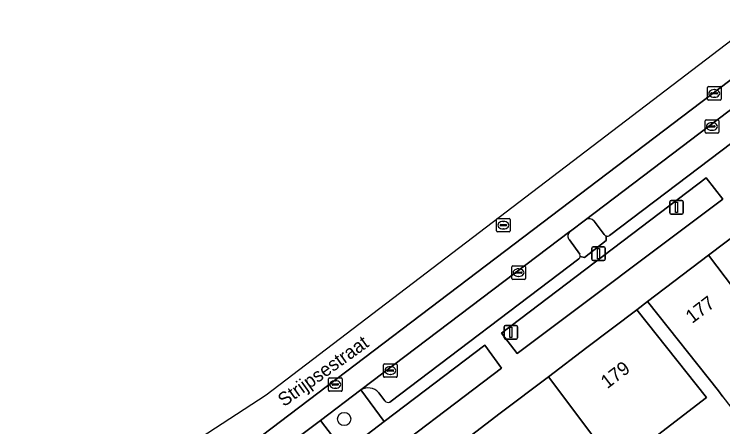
# Model space of a CAD drawing. Extents: x 159371 to 159986, y 382987 to 383597.
# Drawn here: x 159435.3 to 159487.5, y 383451 to 383481.4 of the extents above; entities that cross this region are included whole.
import ezdxf

# ---------------------------------------------------------------- set-up
doc = ezdxf.new("R2010")
doc.units = 0
for name, color, linetype in [('IMGEO_Boom', 7, 'Continuous'), ('IMGEO_Erf', 7, 'Continuous'), ('IMGEO_Groenvoorziening', 7, 'Continuous'), ('IMGEO_Kolk', 7, 'Continuous'), ('IMGEO_Lichtmast', 7, 'Continuous'), ('IMGEO_Openbare_ruimte_label', 7, 'Continuous'), ('IMGEO_Pand', 7, 'Continuous'), ('IMGEO_Pand_nummerreeks', 7, 'Continuous'), ('IMGEO_Parkeervlak_open', 7, 'Continuous'), ('IMGEO_Rijbaan_lokaal_gesloten', 7, 'Continuous'), ('IMGEO_Rijbaan_regionaal_open', 7, 'Continuous'), ('IMGEO_Rioolput', 7, 'Continuous'), ('IMGEO_Voetpad_open', 7, 'Continuous')]:
    doc.layers.add(name, color=color, linetype=linetype)

msp = doc.modelspace()

# ---------------------------------------------------------------- linework, layer by layer
at = {"layer": 'IMGEO_Boom'}
msp.add_circle((159459.611, 383451.55), 0.489, dxfattribs=at)
at = {"layer": 'IMGEO_Erf'}
msp.add_lwpolyline([(159487.559, 383453.189), (159487.219, 383453.635), (159481.987, 383460.213), (159481.199, 383459.608), (159486.357, 383453.128), (159482.085, 383449.87)], dxfattribs=at)
at = {"layer": 'IMGEO_Groenvoorziening'}
for points in [[(159472.377, 383456.378), (159487.545, 383467.769), (159486.332, 383469.328), (159471.229, 383457.872)], [(159471.23, 383455.311), (159469.992, 383456.988), (159462.575, 383451.365), (159459.638, 383449.137), (159460.912, 383447.483)], [(159460.832, 383453.708), (159457.863, 383451.442), (159459.638, 383449.137), (159462.575, 383451.365)]]:
    msp.add_lwpolyline(points, close=True, dxfattribs=at)
for points in [[(159477.407, 383466.243), (159476.315, 383465.414), (159476.264, 383465.375)], [(159478.804, 383465.148), (159478.062, 383466.146)], [(159477.024, 383463.535), (159477.339, 383463.475), (159478.937, 383464.718), (159478.954, 383465.057)], [(159476.226, 383464.764), (159477.01, 383463.705)]]:
    msp.add_lwpolyline(points, dxfattribs=at)
for centre, radius, start, end in [((159477.678, 383465.811), 0.51, 41.0938, 122.0586), ((159476.549, 383465.051), 0.432, 131.2827, 221.5997), ((159479.041, 383465.369), 0.324, 223.0627, 254.4497), ((159476.694, 383463.593), 0.335, 349.9501, 19.4656)]:
    msp.add_arc(centre, radius, start, end, dxfattribs=at)
at = {"layer": 'IMGEO_Kolk'}
for p, q in [((159486.243, 383472.699), (159486.243, 383473.551)), ((159486.318, 383473.625), (159487.17, 383473.625)), ((159486.731, 383473.405), (159486.756, 383473.405)), ((159487.244, 383473.551), (159487.244, 383472.699)), ((159486.502, 383473.119), (159486.502, 383473.131)), ((159486.94, 383473.082), (159486.542, 383473.082)), ((159486.545, 383473.168), (159486.943, 383473.168)), ((159486.754, 383472.845), (159486.729, 383472.845)), ((159486.986, 383473.131), (159486.986, 383473.119)), ((159487.17, 383472.625), (159486.318, 383472.625)), ((159471.979, 383461.919), (159471.979, 383462.771)), ((159472.054, 383462.845), (159472.906, 383462.845)), ((159472.281, 383462.388), (159472.679, 383462.388)), ((159472.467, 383462.625), (159472.492, 383462.625)), ((159472.98, 383462.771), (159472.98, 383461.919)), ((159472.906, 383461.845), (159472.054, 383461.845)), ((159472.238, 383462.339), (159472.238, 383462.351)), ((159472.676, 383462.302), (159472.278, 383462.302)), ((159472.49, 383462.065), (159472.465, 383462.065)), ((159472.722, 383462.351), (159472.722, 383462.339)), ((159462.596, 383455.624), (159463.448, 383455.624)), ((159462.521, 383454.698), (159462.521, 383455.55)), ((159462.78, 383455.118), (159462.78, 383455.13)), ((159463.218, 383455.081), (159462.82, 383455.081)), ((159462.823, 383455.167), (159463.221, 383455.167)), ((159463.009, 383455.404), (159463.034, 383455.404)), ((159463.264, 383455.13), (159463.264, 383455.118)), ((159463.522, 383455.55), (159463.522, 383454.698)), ((159463.448, 383454.624), (159462.596, 383454.624)), ((159463.032, 383454.844), (159463.007, 383454.844))]:
    msp.add_line(p, q, dxfattribs=at)
for points in [[(159486.243, 383472.699), (159486.243, 383473.551)], [(159486.318, 383473.625), (159487.17, 383473.625)], [(159487.244, 383473.551), (159487.244, 383472.699)], [(159487.17, 383472.625), (159486.318, 383472.625)], [(159471.979, 383461.919), (159471.979, 383462.771)], [(159472.054, 383462.845), (159472.906, 383462.845)], [(159472.98, 383462.771), (159472.98, 383461.919)], [(159472.906, 383461.845), (159472.054, 383461.845)], [(159462.596, 383455.624), (159463.448, 383455.624)], [(159462.521, 383454.698), (159462.521, 383455.55)], [(159463.522, 383455.55), (159463.522, 383454.698)], [(159463.448, 383454.624), (159462.596, 383454.624)]]:
    msp.add_lwpolyline(points, dxfattribs=at)
for centre, radius, start, end in [((159486.32, 383473.549), 0.0765, 91.552, 178.448), ((159486.32, 383473.549), 0.0765, 91.552, 178.448), ((159487.168, 383473.549), 0.0765, 1.552, 88.448), ((159487.168, 383473.549), 0.0765, 1.552, 88.448), ((159486.542, 383473.128), 0.0403, 85.8775, 175.7526), ((159486.539, 383473.118), 0.0366, 178.938, 274.7102), ((159486.943, 383473.125), 0.043, 264.8664, 352.4533), ((159486.947, 383473.13), 0.0386, 1.7309, 96.639), ((159486.32, 383472.701), 0.0765, 181.552, 268.448), ((159486.32, 383472.701), 0.0765, 181.552, 268.448), ((159487.168, 383472.701), 0.0765, 271.552, 358.448), ((159487.168, 383472.701), 0.0765, 271.552, 358.448), ((159472.056, 383462.769), 0.0765, 91.552, 178.448), ((159472.056, 383462.769), 0.0765, 91.552, 178.448), ((159472.278, 383462.348), 0.0403, 85.8775, 175.7526), ((159472.683, 383462.35), 0.0386, 1.7309, 96.639), ((159472.904, 383462.769), 0.0765, 1.552, 88.448), ((159472.904, 383462.769), 0.0765, 1.552, 88.448), ((159472.056, 383461.921), 0.0765, 181.552, 268.448), ((159472.056, 383461.921), 0.0765, 181.552, 268.448), ((159472.275, 383462.338), 0.0366, 178.938, 274.7102), ((159472.679, 383462.345), 0.043, 264.8664, 352.4533), ((159472.904, 383461.921), 0.0765, 271.552, 358.448), ((159472.904, 383461.921), 0.0765, 271.552, 358.448), ((159462.598, 383455.548), 0.0765, 91.552, 178.448), ((159462.598, 383455.548), 0.0765, 91.552, 178.448), ((159463.446, 383455.548), 0.0765, 1.552, 88.448), ((159463.446, 383455.548), 0.0765, 1.552, 88.448), ((159462.82, 383455.127), 0.0403, 85.8775, 175.7526), ((159462.817, 383455.117), 0.0366, 178.938, 274.7102), ((159463.221, 383455.124), 0.043, 264.8664, 352.4533), ((159463.225, 383455.129), 0.0386, 1.7309, 96.639), ((159462.598, 383454.7), 0.0765, 181.552, 268.448), ((159462.598, 383454.7), 0.0765, 181.552, 268.448), ((159463.446, 383454.7), 0.0765, 271.552, 358.448), ((159463.446, 383454.7), 0.0765, 271.552, 358.448)]:
    msp.add_arc(centre, radius, start, end, dxfattribs=at)
for centre, major_axis, ratio, start_param, end_param in [((159486.73, 383473.125), (-0.387, 0.002), 0.722429, 4.712389, 7.853982), ((159486.755, 383473.125), (-0.39, 0.002), 0.717154, 1.570796, 4.712389), ((159472.466, 383462.345), (-0.387, 0.002), 0.722429, 4.712389, 7.853982), ((159472.491, 383462.345), (-0.39, 0.002), 0.717154, 1.570796, 4.712389), ((159463.008, 383455.124), (-0.387, 0.002), 0.722429, 4.712389, 7.853982), ((159463.033, 383455.124), (-0.39, 0.002), 0.717154, 1.570796, 4.712389)]:
    msp.add_ellipse(centre, major_axis=major_axis, ratio=ratio, start_param=start_param, end_param=end_param, dxfattribs=at)
at = {"layer": 'IMGEO_Lichtmast'}
for p, q in [((159483.734, 383467.666), (159484.524, 383467.666)), ((159484.524, 383467.666), (159483.734, 383467.666)), ((159483.634, 383466.766), (159483.634, 383467.566)), ((159483.634, 383467.566), (159483.634, 383466.766)), ((159484.624, 383467.566), (159484.624, 383466.766)), ((159484.624, 383466.766), (159484.624, 383467.566)), ((159484.524, 383466.666), (159483.734, 383466.666)), ((159483.734, 383466.666), (159484.524, 383466.666)), ((159477.876, 383463.344), (159477.876, 383464.144)), ((159477.876, 383464.144), (159477.876, 383463.344)), ((159477.976, 383464.244), (159478.766, 383464.244)), ((159478.766, 383464.244), (159477.976, 383464.244)), ((159478.866, 383464.144), (159478.866, 383463.344)), ((159478.866, 383463.344), (159478.866, 383464.144)), ((159478.766, 383463.244), (159477.976, 383463.244)), ((159477.976, 383463.244), (159478.766, 383463.244)), ((159471.423, 383457.547), (159471.423, 383458.347)), ((159471.423, 383458.347), (159471.423, 383457.547)), ((159471.523, 383458.447), (159472.313, 383458.447)), ((159472.313, 383458.447), (159471.523, 383458.447)), ((159472.413, 383458.347), (159472.413, 383457.547)), ((159472.413, 383457.547), (159472.413, 383458.347)), ((159472.313, 383457.447), (159471.523, 383457.447)), ((159471.523, 383457.447), (159472.313, 383457.447))]:
    msp.add_line(p, q, dxfattribs=at)
for points in [[(159484.054, 383467.541), (159484.204, 383467.541), (159484.204, 383466.791), (159484.054, 383466.791), (159484.054, 383467.541)], [(159478.296, 383464.119), (159478.446, 383464.119), (159478.446, 383463.369), (159478.296, 383463.369), (159478.296, 383464.119)], [(159471.843, 383458.322), (159471.993, 383458.322), (159471.993, 383457.572), (159471.843, 383457.572), (159471.843, 383458.322)]]:
    msp.add_lwpolyline(points, dxfattribs=at)
for centre, start, end in [((159483.734, 383467.566), 90, 180), ((159483.734, 383467.566), 90, 180), ((159484.524, 383467.566), 0, 90), ((159484.524, 383467.566), 360, 90), ((159483.734, 383466.766), 180, 270), ((159483.734, 383466.766), 180, 270), ((159484.524, 383466.766), 270, 0), ((159484.524, 383466.766), 270, 0), ((159477.976, 383464.144), 90, 180), ((159477.976, 383464.144), 90, 180), ((159478.766, 383464.144), 0, 90), ((159478.766, 383464.144), 360, 90), ((159477.976, 383463.344), 180, 270), ((159477.976, 383463.344), 180, 270), ((159478.766, 383463.344), 270, 0), ((159478.766, 383463.344), 270, 0), ((159471.523, 383458.347), 90, 180), ((159471.523, 383458.347), 90, 180), ((159472.313, 383458.347), 0, 90), ((159472.313, 383458.347), 360, 90), ((159471.523, 383457.547), 180, 270), ((159471.523, 383457.547), 180, 270), ((159472.313, 383457.547), 270, 0), ((159472.313, 383457.547), 270, 0)]:
    msp.add_arc(centre, 0.1, start, end, dxfattribs=at)
at = {"layer": 'IMGEO_Pand'}
for points in [[(159491.499, 383467.432), (159491.306, 383467.285), (159486.499, 383463.639), (159492.574, 383455.621), (159493.049, 383455.984), (159497.581, 383459.441)], [(159486.499, 383463.639), (159481.987, 383460.213), (159487.219, 383453.635), (159487.559, 383453.189), (159488.719, 383451.668), (159489.19, 383452.028), (159489.948, 383452.606), (159493.061, 383454.981), (159492.574, 383455.621)], [(159486.357, 383453.128), (159481.199, 383459.608), (159477.515, 383456.814), (159474.69, 383454.671), (159483.863, 383442.437), (159486.771, 383444.655), (159483.379, 383449.1), (159482.932, 383448.76), (159482.085, 383449.87)], [(159474.69, 383454.671), (159471.132, 383451.972), (159468.26, 383449.798), (159473.548, 383443.275), (159474.921, 383444.321), (159475.976, 383442.938), (159476.152, 383442.708), (159476.258, 383442.569), (159478.466, 383444.254), (159481.328, 383440.503), (159481.545, 383438.838), (159484.542, 383439.548), (159483.863, 383442.437)]]:
    msp.add_lwpolyline(points, close=True, dxfattribs=at)
at = {"layer": 'IMGEO_Parkeervlak_open'}
for points in [[(159492.914, 383477.993), (159477.407, 383466.243)], [(159479.198, 383465.082), (159493.171, 383475.68)], [(159478.062, 383466.146), (159478.804, 383465.148)], [(159476.264, 383465.375), (159460.832, 383453.708)], [(159477.01, 383463.705), (159476.226, 383464.764)], [(159462.991, 383452.803), (159476.934, 383463.36)], [(159462.168, 383453.488), (159462.606, 383452.885)]]:
    msp.add_lwpolyline(points, dxfattribs=at)
for centre, radius, start, end in [((159477.678, 383465.811), 0.51, 41.0938, 122.0586), ((159476.549, 383465.051), 0.432, 131.2827, 221.5997), ((159479.041, 383465.369), 0.324, 223.0627, 254.4497), ((159479.045, 383465.375), 0.331, 254.0814, 297.6187), ((159476.689, 383463.597), 0.34, 315.9792, 349.5885), ((159476.694, 383463.593), 0.335, 349.9501, 19.4656), ((159461.366, 383452.781), 1.069, 41.3626, 119.9354), ((159462.86, 383453.132), 0.354, 224.1996, 291.7532)]:
    msp.add_arc(centre, radius, start, end, dxfattribs=at)
at = {"layer": 'IMGEO_Rijbaan_lokaal_gesloten'}
msp.add_lwpolyline([(159427.129, 383428.173), (159427.859, 383428.709), (159429.817, 383430.216), (159435.428, 383434.471), (159435.864, 383434.831), (159435.968, 383434.909), (159451.798, 383446.86), (159453.424, 383448.091), (159457.863, 383451.442), (159460.832, 383453.708), (159476.264, 383465.375), (159476.315, 383465.414), (159477.407, 383466.243), (159492.914, 383477.993), (159494.529, 383479.229), (159494.976, 383479.535), (159493.954, 383480.98), (159492.14, 383479.622), (159434.929, 383436.186), (159424.779, 383428.544)], dxfattribs=at)
at = {"layer": 'IMGEO_Rijbaan_regionaal_open'}
msp.add_lwpolyline([(159424.779, 383428.544), (159434.929, 383436.186), (159492.14, 383479.622), (159490.734, 383481.412), (159453.87, 383453.311), (159440.381, 383444.531), (159430.515, 383438.11), (159401.313, 383419.104)], dxfattribs=at)
at = {"layer": 'IMGEO_Rioolput'}
for p, q in [((159486.416, 383475.142), (159486.416, 383475.994)), ((159486.491, 383476.068), (159487.343, 383476.068)), ((159487.417, 383475.994), (159487.417, 383475.142)), ((159486.675, 383475.562), (159486.675, 383475.574)), ((159487.113, 383475.525), (159486.715, 383475.525)), ((159486.718, 383475.611), (159487.116, 383475.611)), ((159486.904, 383475.848), (159486.929, 383475.848)), ((159487.159, 383475.574), (159487.159, 383475.562)), ((159487.343, 383475.068), (159486.491, 383475.068)), ((159486.927, 383475.288), (159486.902, 383475.288)), ((159470.859, 383465.421), (159470.859, 383466.273)), ((159470.934, 383466.347), (159471.786, 383466.347)), ((159471.347, 383466.127), (159471.372, 383466.127)), ((159471.86, 383466.273), (159471.86, 383465.421)), ((159471.118, 383465.841), (159471.118, 383465.853)), ((159471.556, 383465.804), (159471.158, 383465.804)), ((159471.161, 383465.89), (159471.559, 383465.89)), ((159471.37, 383465.567), (159471.345, 383465.567)), ((159471.602, 383465.853), (159471.602, 383465.841)), ((159471.786, 383465.347), (159470.934, 383465.347)), ((159458.454, 383453.667), (159458.454, 383454.519)), ((159458.529, 383454.593), (159459.381, 383454.593)), ((159459.455, 383454.519), (159459.455, 383453.667)), ((159458.713, 383454.087), (159458.713, 383454.099)), ((159459.151, 383454.05), (159458.753, 383454.05)), ((159458.756, 383454.136), (159459.154, 383454.136)), ((159458.942, 383454.373), (159458.967, 383454.373)), ((159459.197, 383454.099), (159459.197, 383454.087)), ((159459.381, 383453.593), (159458.529, 383453.593)), ((159458.965, 383453.813), (159458.94, 383453.813))]:
    msp.add_line(p, q, dxfattribs=at)
for points in [[(159486.416, 383475.142), (159486.416, 383475.994)], [(159486.491, 383476.068), (159487.343, 383476.068)], [(159487.417, 383475.994), (159487.417, 383475.142)], [(159487.343, 383475.068), (159486.491, 383475.068)], [(159470.859, 383465.421), (159470.859, 383466.273)], [(159470.934, 383466.347), (159471.786, 383466.347)], [(159471.86, 383466.273), (159471.86, 383465.421)], [(159471.786, 383465.347), (159470.934, 383465.347)], [(159458.454, 383453.667), (159458.454, 383454.519)], [(159458.529, 383454.593), (159459.381, 383454.593)], [(159459.455, 383454.519), (159459.455, 383453.667)], [(159459.381, 383453.593), (159458.529, 383453.593)]]:
    msp.add_lwpolyline(points, dxfattribs=at)
for centre, radius, start, end in [((159486.493, 383475.992), 0.0765, 91.552, 178.448), ((159486.493, 383475.992), 0.0765, 91.552, 178.448), ((159487.341, 383475.992), 0.0765, 1.552, 88.448), ((159487.341, 383475.992), 0.0765, 1.552, 88.448), ((159486.715, 383475.571), 0.0403, 85.8775, 175.7526), ((159486.712, 383475.561), 0.0366, 178.938, 274.7102), ((159487.116, 383475.568), 0.043, 264.8664, 352.4533), ((159487.12, 383475.573), 0.0386, 1.7309, 96.639), ((159486.493, 383475.144), 0.0765, 181.552, 268.448), ((159486.493, 383475.144), 0.0765, 181.552, 268.448), ((159487.341, 383475.144), 0.0765, 271.552, 358.448), ((159487.341, 383475.144), 0.0765, 271.552, 358.448), ((159470.936, 383466.271), 0.0765, 91.552, 178.448), ((159470.936, 383466.271), 0.0765, 91.552, 178.448), ((159471.784, 383466.271), 0.0765, 1.552, 88.448), ((159471.784, 383466.271), 0.0765, 1.552, 88.448), ((159471.158, 383465.85), 0.0403, 85.8775, 175.7526), ((159471.155, 383465.84), 0.0366, 178.938, 274.7102), ((159471.559, 383465.847), 0.043, 264.8664, 352.4533), ((159471.563, 383465.852), 0.0386, 1.7309, 96.639), ((159470.936, 383465.423), 0.0765, 181.552, 268.448), ((159470.936, 383465.423), 0.0765, 181.552, 268.448), ((159471.784, 383465.423), 0.0765, 271.552, 358.448), ((159471.784, 383465.423), 0.0765, 271.552, 358.448), ((159458.531, 383454.517), 0.0765, 91.552, 178.448), ((159458.531, 383454.517), 0.0765, 91.552, 178.448), ((159459.379, 383454.517), 0.0765, 1.552, 88.448), ((159459.379, 383454.517), 0.0765, 1.552, 88.448), ((159458.753, 383454.096), 0.0403, 85.8775, 175.7526), ((159458.75, 383454.086), 0.0366, 178.938, 274.7102), ((159459.154, 383454.093), 0.043, 264.8664, 352.4533), ((159459.158, 383454.098), 0.0386, 1.7309, 96.639), ((159458.531, 383453.669), 0.0765, 181.552, 268.448), ((159458.531, 383453.669), 0.0765, 181.552, 268.448), ((159459.379, 383453.669), 0.0765, 271.552, 358.448), ((159459.379, 383453.669), 0.0765, 271.552, 358.448)]:
    msp.add_arc(centre, radius, start, end, dxfattribs=at)
for centre, major_axis, ratio, start_param, end_param in [((159486.903, 383475.568), (-0.387, 0.002), 0.722429, 4.712389, 7.853982), ((159486.928, 383475.568), (-0.39, 0.002), 0.717154, 1.570796, 4.712389), ((159471.346, 383465.847), (-0.387, 0.002), 0.722429, 4.712389, 7.853982), ((159471.371, 383465.847), (-0.39, 0.002), 0.717154, 1.570796, 4.712389), ((159458.941, 383454.093), (-0.387, 0.002), 0.722429, 4.712389, 7.853982), ((159458.966, 383454.093), (-0.39, 0.002), 0.717154, 1.570796, 4.712389)]:
    msp.add_ellipse(centre, major_axis=major_axis, ratio=ratio, start_param=start_param, end_param=end_param, dxfattribs=at)
at = {"layer": 'IMGEO_Voetpad_open'}
for points in [[(159452.734, 383439.412), (159453.314, 383438.652), (159459.401, 383443.31), (159459.554, 383443.427), (159459.676, 383443.267), (159461.209, 383444.451), (159461.945, 383445.02), (159467.302, 383449.158), (159468.26, 383449.798), (159471.132, 383451.972), (159474.69, 383454.671), (159477.515, 383456.814), (159481.199, 383459.608), (159481.987, 383460.213), (159486.499, 383463.639), (159491.306, 383467.285), (159491.499, 383467.432), (159496.066, 383470.906), (159500.039, 383473.929), (159500.731, 383474.456), (159503.767, 383476.741), (159502.534, 383478.452)], [(159493.171, 383475.68), (159479.198, 383465.082)], [(159478.954, 383465.057), (159478.937, 383464.718), (159477.339, 383463.475), (159477.024, 383463.535)], [(159476.934, 383463.36), (159462.991, 383452.803)], [(159460.832, 383453.708), (159462.575, 383451.365), (159469.992, 383456.988), (159471.23, 383455.311), (159460.912, 383447.483), (159459.638, 383449.137), (159457.863, 383451.442), (159453.424, 383448.091), (159455.197, 383445.768), (159456.453, 383444.122), (159449.382, 383438.72), (159448.106, 383440.412), (159453.552, 383444.521), (159451.798, 383446.86)], [(159462.606, 383452.885), (159462.168, 383453.488)]]:
    msp.add_lwpolyline(points, dxfattribs=at)
msp.add_lwpolyline([(159472.377, 383456.378), (159471.229, 383457.872), (159486.332, 383469.328), (159487.545, 383467.769)], close=True, dxfattribs=at)
for centre, radius, start, end in [((159479.045, 383465.375), 0.331, 254.0814, 297.6187), ((159476.689, 383463.597), 0.34, 315.9792, 349.5885), ((159461.366, 383452.781), 1.069, 41.3626, 119.9354), ((159462.86, 383453.132), 0.354, 224.1996, 291.7532)]:
    msp.add_arc(centre, radius, start, end, dxfattribs=at)

# ---------------------------------------------------------------- texts
at = {"layer": 'IMGEO_Openbare_ruimte_label'}
msp.add_text('Strijpsestraat', height=1, rotation=35.5976, dxfattribs=at).set_placement((159455.172, 383452.414))
at = {"layer": 'IMGEO_Pand_nummerreeks'}
for s, rotation, p in [('177', 37.2766, (159485.284, 383458.555)), ('179', 37.3397, (159479.023, 383453.744))]:
    msp.add_text(s, height=1, rotation=rotation, dxfattribs=at).set_placement(p)

doc.saveas('drawing.dxf')
